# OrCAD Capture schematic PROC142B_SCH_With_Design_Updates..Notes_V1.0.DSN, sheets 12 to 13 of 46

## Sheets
12 10. USB TYPE-C POWER: size C; title: USB TYPE-C PD CONTROLLER AND POWER SUPPLY
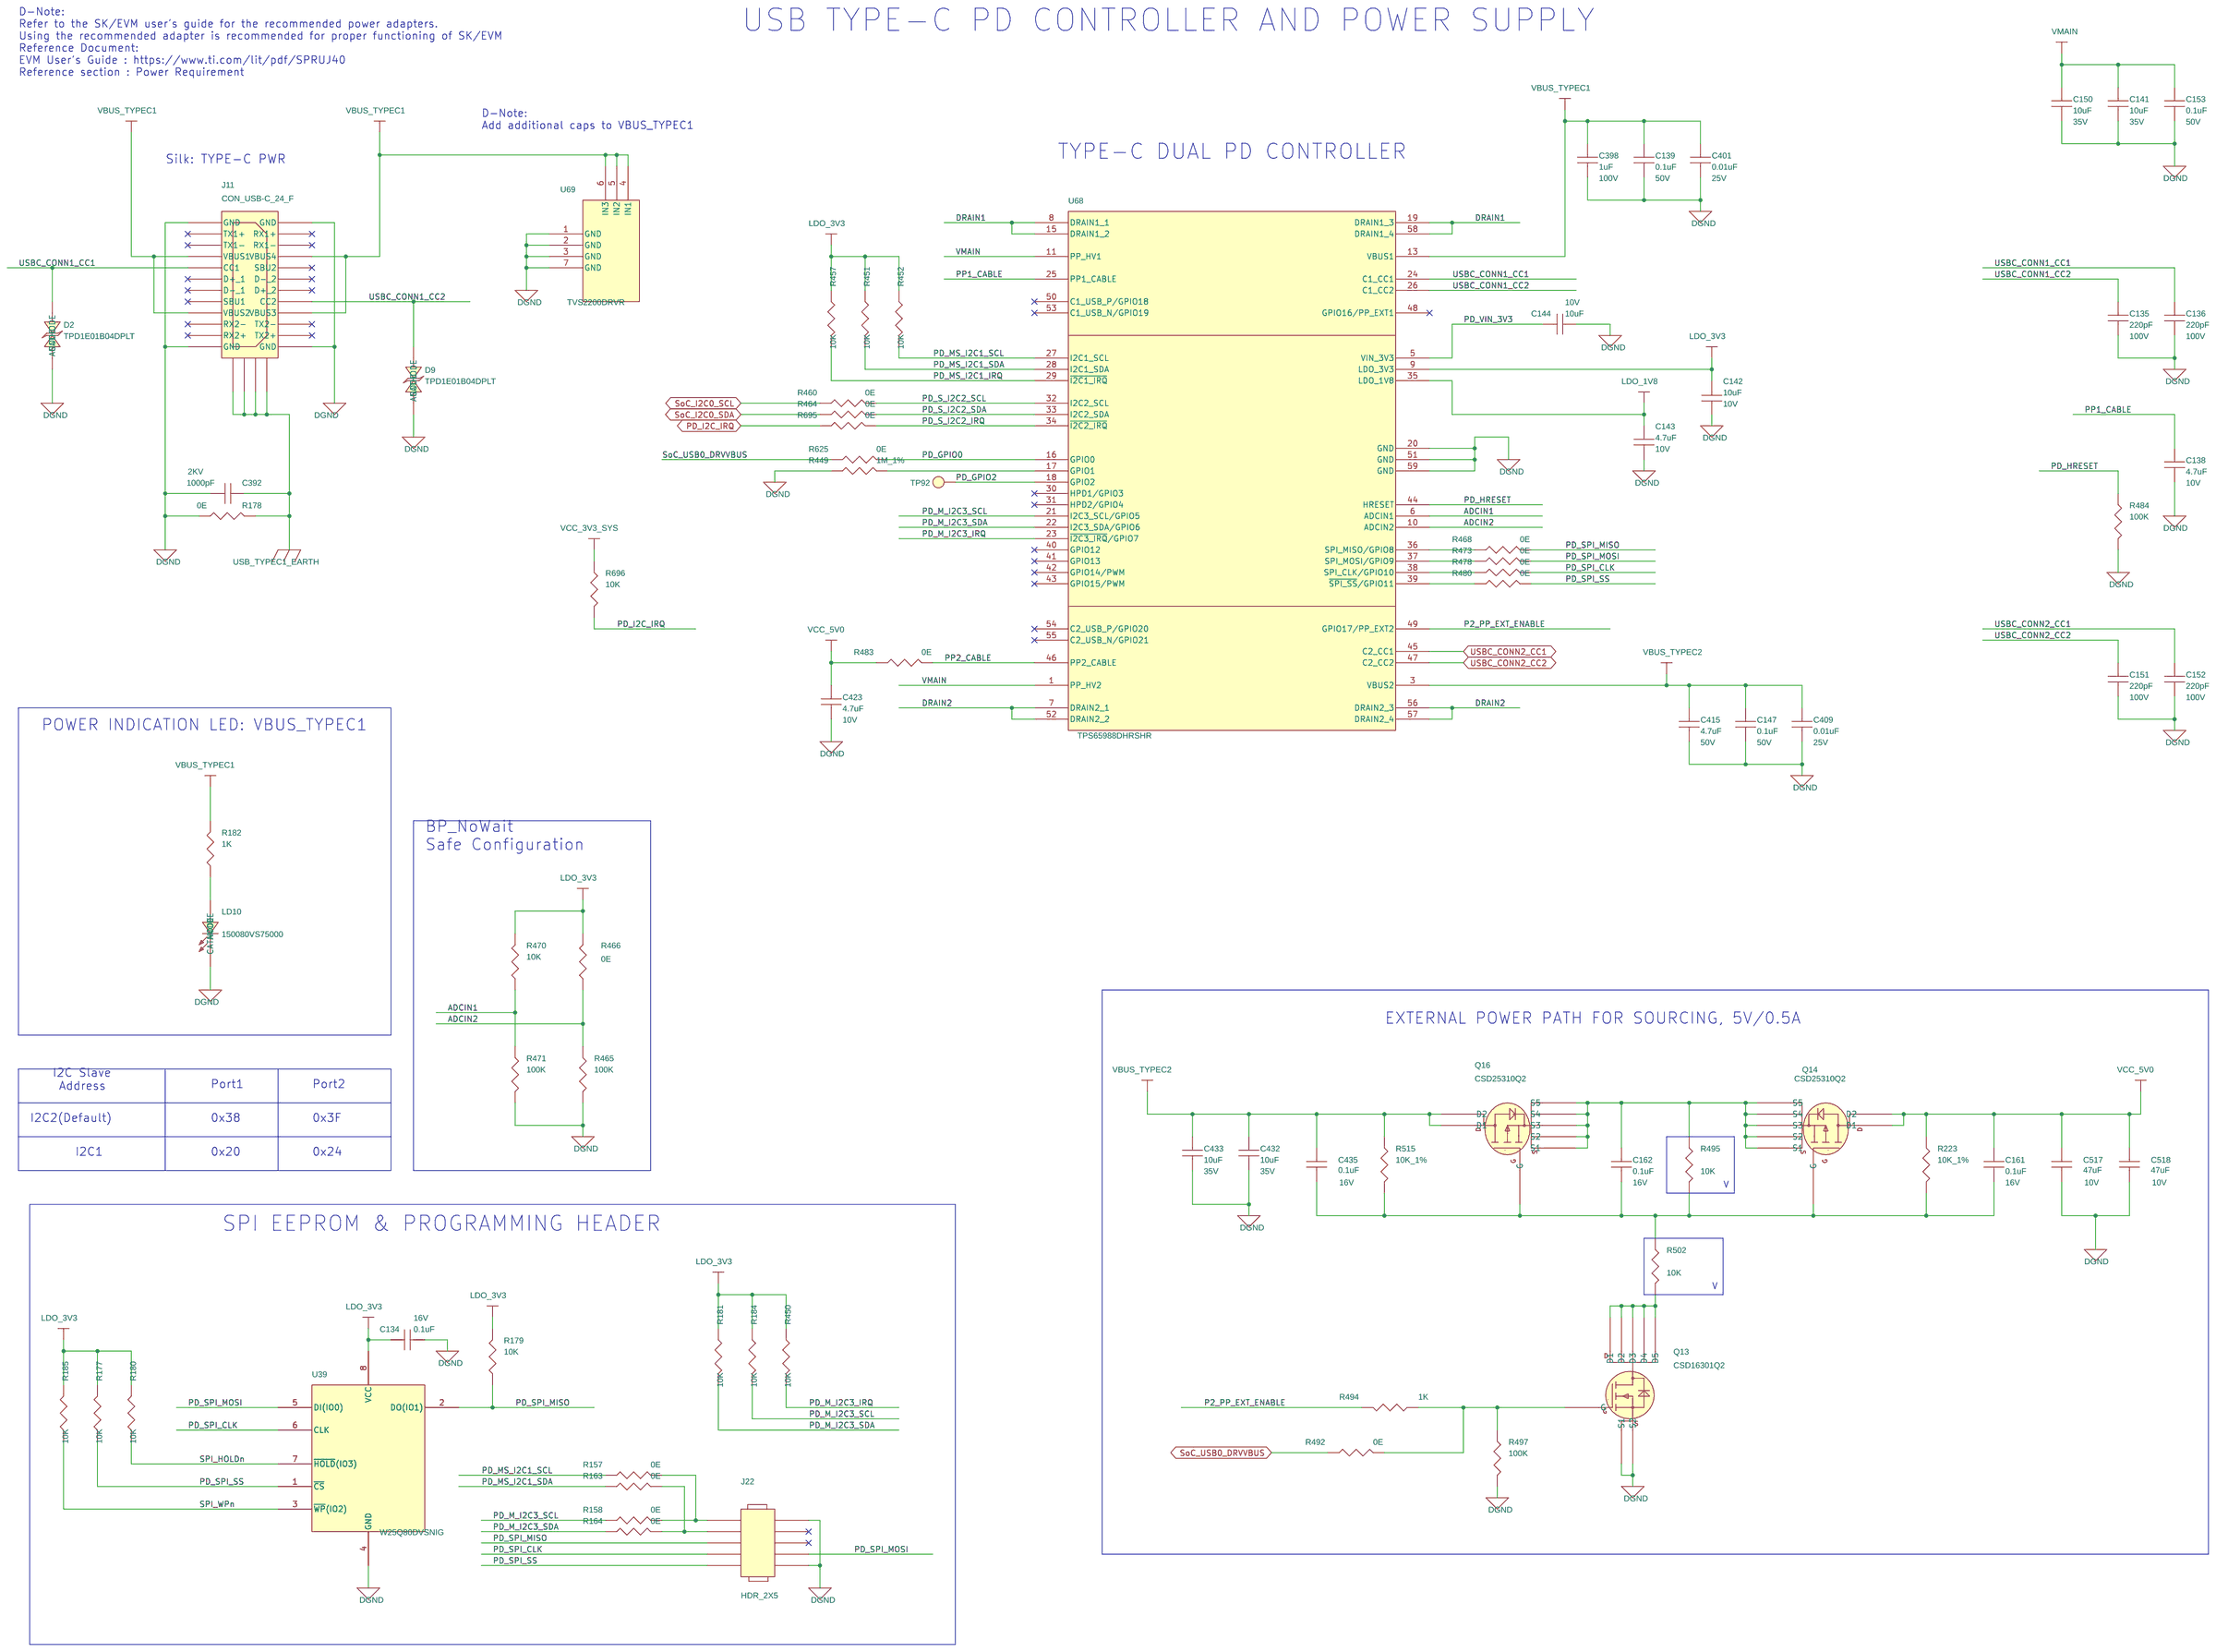
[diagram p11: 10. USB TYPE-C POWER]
13 11. PERIPHERAL POWER SUPPLY-1: size C; title: PERIPHERAL POWER SUPPLIES-1
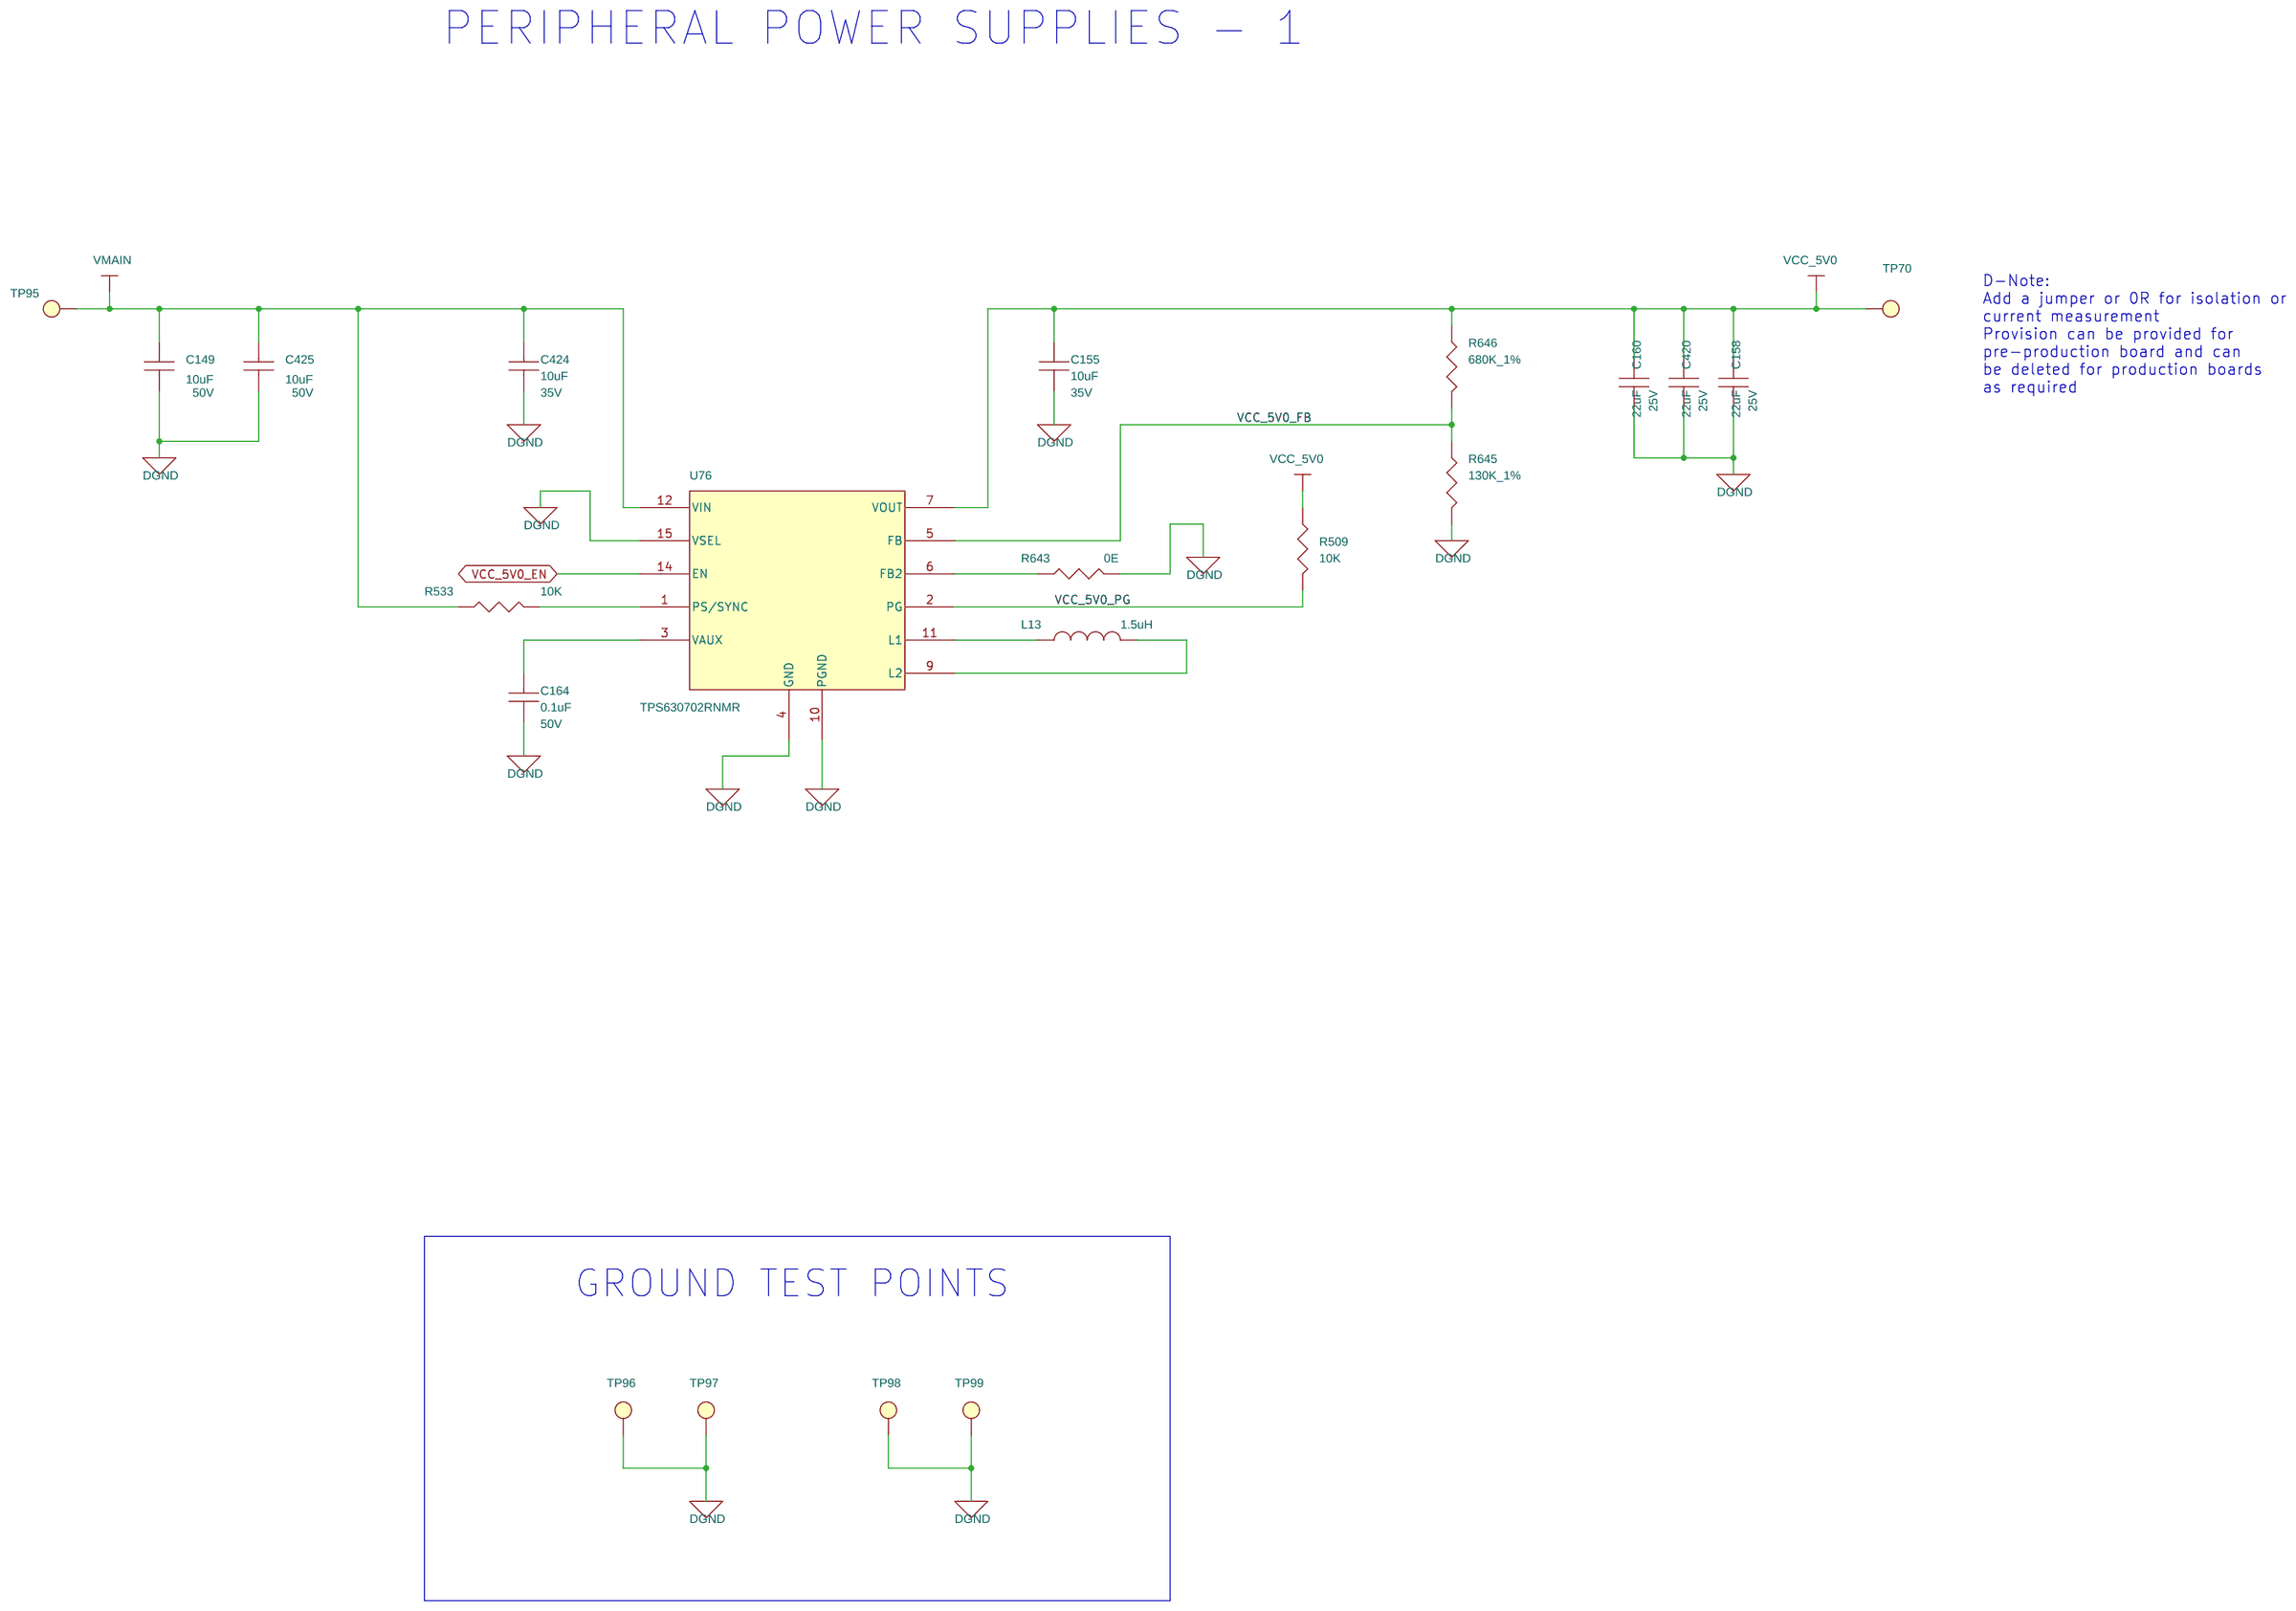
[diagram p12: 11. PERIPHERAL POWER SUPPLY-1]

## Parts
sheet 10. USB TYPE-C POWER
C134  0.1uF  [CAP0201_0-5]
C135  220pF  [CAP0402_0-75]
C136  220pF  [CAP0402_0-75]
C138  4.7uF  [CAP0402_0-75]
C139  0.1uF  [CAP0402_0-75]
C141  10uF  [CAP0603_1]
C142  10uF  [CAP0402_0-75]
C143  4.7uF  [CAP0402_0-75]
C144  10uF  [CAP0402_0-75]
C147  0.1uF  [CAP0402_0-75]
C150  10uF  [CAP0603_1]
C151  220pF  [CAP0402_0-75]
C152  220pF  [CAP0402_0-75]
C153  0.1uF  [CAP0402_0-75]
C161  0.1uF  [CAP0201_0-5]
C162  0.1uF  [CAP0201_0-5]
C392  1000pF  [CAP1206_1-75]
C398  1uF  [CAP0805_1-5]
C401  0.01uF  [CAP0201_0-5]
C409  0.01uF  [CAP0201_0-5]
C415  4.7uF  [CAP0805_1-5]
C423  4.7uF  [CAP0402_0-75]
C432  10uF  [CAP0603_1]
C433  10uF  [CAP0603_1]
C435  0.1uF  [CAP0201_0-5]
C517  47uF  [CAP1206_2]
C518  47uF  [CAP1206_2]
D2  TPD1E01B04DPLT  [DIO_DFN0201_0-4]
D9  TPD1E01B04DPLT  [DIO_DFN0201_0-4]
J11  CON_USB-C_24_F  [CON_USBC24_2012670_S_R_S_3-9]
J22  HDR_2X5  [HDR_2X5_PEC05DAAN_S_T_8-6]
LD10  150080VS75000  [LED_150080VS75000_80X50_SMD_0-8]
Q13  CSD16301Q2  [WSON6_CSD13202Q2_80X80_0-8]
Q14  CSD25310Q2  [SON6_CSD17313Q2_80X80]
Q16  CSD25310Q2  [SON6_CSD17313Q2_80X80]
R157  0E  [RES0201_0-5]
R158  0E  [RES0201_0-5]
R163  0E  [RES0201_0-5]
R164  0E  [RES0201_0-5]
R177  10K  [RES0201_0-5]
R178  0E  [RES0603_0-75]
R179  10K  [RES0201_0-5]
R180  10K  [RES0201_0-5]
R181  10K  [RES0201_0-5]
R182  1K  [RES0402_0-5]
R184  10K  [RES0201_0-5]
R185  10K  [RES0201_0-5]
R223  10K_1%  [RES0201_0-5]
R449  1M_1%  [RES0402_0-5]
R450  10K  [RES0201_0-5]
R451  10K  [RES0201_0-5]
R452  10K  [RES0201_0-5]
R457  10K  [RES0201_0-5]
R460  0E  [RES0201_0-5]
R464  0E  [RES0201_0-5]
R465  100K  [RES0402_0-5]
R466  0E  [RES0402_0-5]
R468  0E  [RES0201_0-5]
R470  10K  [RES0402_0-5]
R471  100K  [RES0402_0-5]
R473  0E  [RES0201_0-5]
R478  0E  [RES0201_0-5]
R480  0E  [RES0201_0-5]
R483  0E  [RES0402_0-5]
R484  100K  [RES0201_0-5]
R492  0E  [RES0201_0-5]
R494  1K  [RES0402_0-5]
R495  10K  [RES0201_0-5]
R497  100K  [RES0402_0-5]
R502  10K  [RES0201_0-5]
R515  10K_1%  [RES0201_0-5]
R625  0E  [RES0201_0-5]
R695  0E  [RES0201_0-5]
R696  10K  [RES0201_0-5]
TP92  TP20_SMD  [TP20_SMD]
U39  W25Q80DVSNIG  [SOIC8_1-8]
U68  TPS65988DHRSHR  [VQFN56_TPS65987D_280X280_1]
U69  TVS2200DRVR  [SON6_25-59_85X85_0-8]
sheet 11. PERIPHERAL POWER SUPPLY-1
C149  10uF  [CAP0805_1-5]
C155  10uF  [CAP0603_1]
C158  22uF  [CAP0805_1-5]
C160  22uF  [CAP0805_1-5]
C164  0.1uF  [CAP0402_0-75]
C420  22uF  [CAP0805_1-5]
C424  10uF  [CAP0603_1]
C425  10uF  [CAP0805_1-5]
L13  1.5uH  [IND_XFL4020_170X170_SMD_2-1]
R509  10K  [RES0402_0-5]
R533  10K  [RES0402_0-5]
R643  0E  [RES0201_0-5]
R645  130K_1%  [RES0402_0-5]
R646  680K_1%  [RES0402_0-5]
TP70  TP20_SMD  [TP20_SMD]
TP95  TP20_SMD  [TP20_SMD]
TP96  THRU HOLE  [TP_36X22]
TP97  THRU HOLE  [TP_36X22]
TP98  TP20_SMD  [TP20_SMD]
TP99  TP20_SMD  [TP20_SMD]
U76  TPS630702RNMR  [VQFNHR15_TPS630701_100X120_1]

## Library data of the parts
C134 C161 C162 C435 = CAP: CAP CERAMIC 0.1uF 16V 10% X5R 0201; Chkd/date: MANIRAJA/230118; Crtd /date: MANIRAJA/230118; Custom_Duty: 15%; Customs_HS_Code: 85322990; Distributor_name: DIGIKEY; Distributor_part_number: 490-14305-1-ND; Footprint Path: Y:\MIS_DATABASE\Library\ALTIUM_TOOL\PCB_FOOTPRINTS\Altium_Footprint_Lib.PcbLib; Height: 0.33MM; Library Path: Y:\MIS_DATABASE\Library\ALTIUM_TOOL\SCHEMATICS_PARTS\MS_DISCRETE_Library.schlib; Mfr_name: MURATA; Mfr_part_number: GRM033R61C104KE14D; Mistral Part No: 120009030072-R; Package: 0201; Part_type: CAPACITORS\CERAMIC; Project: TI_MAXIE_CPB; RoHS: RoHS; Temperature: -55°C+85°C; Tolerance: 10%; Voltage: 16V; Wattage: NA; Weight: 0.33mg; Datasheet: Y:\MIS_DATABASE\DATASHEETS\CAPACITORS\GRM033R61C104KE14.PDF
C135 C136 C151 C152 = CAP: CAP CERAMIC 220pF 100V 5% C0G(NP0) 0402; Chkd/date: MANIRAJA/061021; Crtd /date: ALVY/051021; Custom_Duty: 15%; Customs_HS_Code: 85322990; Distributor_name: DIGIKEY; Distributor_part_number: 490-GRM1555C2A221JE01DTR-ND; Footprint Path: Y:\MIS_DATABASE\Library\ALTIUM_TOOL\PCB_FOOTPRINTS\Altium_Footprint_Lib.PcbLib; Height: 0.55MM; Library Path: Y:\MIS_DATABASE\Library\ALTIUM_TOOL\SCHEMATICS_PARTS\MS_DISCRETE_Library.schlib; Mfr_name: MURATA; Mfr_part_number: GRM1555C2A221JE01D; Mistral Part No: 120021100001-R; Package: 0402; Part_type: CAPACITORS\CERAMIC; Project: TI_AM62x SKEVM_BRD; RoHS: RoHS; Temperature: -55°C+125°C; Tolerance: 5%; Voltage: 100V; Wattage: NA; Weight: 1.6mg; Datasheet: Y:\MIS_DATABASE\DATASHEETS\CAPACITORS\GRM1555C2A221JE01.PDF
C138 C143 C423 = CAP: CAP CERAMIC 4.7uF 10V 20% X5R 0402; Chkd/date: MANIRAJA/110718; Crtd /date: ALVY/110718; Custom_Duty: 15%; Customs_HS_Code: 85322990; Distributor_name: DIGIKEY; Distributor_part_number: 490-14306-1-ND; Footprint Path: Y:\MIS_DATABASE\Library\ALTIUM_TOOL\PCB_FOOTPRINTS\Altium_Footprint_Lib.PcbLib; Height: 0.65MM; Library Path: Y:\MIS_DATABASE\Library\ALTIUM_TOOL\SCHEMATICS_PARTS\MS_DISCRETE_Library.schlib; Mfr_name: MURATA; Mfr_part_number: GRM155R61A475MEAAD; Mistral Part No: 120012060002-R; Package: 0402; Part_type: CAPACITORS\CERAMIC; Project: TI_J7SVB_PCIE_ADD-ON-CARD; RoHS: RoHS; Temperature: -55°C+85°C; Tolerance: 20%; Voltage: 10V; Wattage: NA; Weight: 14mg; Datasheet: Y:\MIS_DATABASE\DATASHEETS\CAPACITORS\GRM155R61A475MEAAD.PDF
C139 C147 C153 C164 = CAP: CAP CERAMIC 0.1uF 50V 10% X7R 0402; Chkd/date: MANIRAJA/261020; Crtd /date: ALVY/211020; Custom_Duty: 15%; Customs_HS_Code: 85322990; Distributor_name: DIGIKEY; Distributor_part_number: 490-10700-1-ND; Footprint Path: Y:\MIS_DATABASE\Library\ALTIUM_TOOL\PCB_FOOTPRINTS\Altium_Footprint_Lib.PcbLib; Height: 0.55MM; Library Path: Y:\MIS_DATABASE\Library\ALTIUM_TOOL\SCHEMATICS_PARTS\MS_DISCRETE_Library.schlib; Mfr_name: MURATA; Mfr_part_number: GRM155R71H104KE14D; Mistral Part No: 120011100014-R; Package: 0402; Part_type: CAPACITORS\CERAMIC; Project: J7_CP; RoHS: RoHS; Temperature: -55°C+125°C; Tolerance: 10%; Voltage: 50V; Wattage: NA; Weight: 3.1mg; Datasheet: Y:\MIS_DATABASE\DATASHEETS\CAPACITORS\GRM155R71H104KE14.PDF
C141 C150 C155 C424 C432 C433 = CAP: CAP CERAMIC 10uF 35V 20% X5R 0603; Chkd/date: MANIRAJA/170519; Crtd /date: ALVY/160519; Custom_Duty: 15%; Customs_HS_Code: 85322990; Distributor_name: DIGIKEY; Distributor_part_number: 490-13248-1-ND; Footprint Path: Y:\MIS_DATABASE\Library\ALTIUM_TOOL\PCB_FOOTPRINTS\Altium_Footprint_Lib.PcbLib; Height: 1.00MM; Library Path: Y:\MIS_DATABASE\Library\ALTIUM_TOOL\SCHEMATICS_PARTS\MS_DISCRETE_Library.schlib; Mfr_name: MURATA; Mfr_part_number: GRM188R6YA106MA73D; Mistral Part No: 120019050016-R; Package: 0603; Part_type: CAPACITORS\CERAMIC; Project: BRUKER_SD820_COMMONDO; RoHS: RoHS; Temperature: -55°C+85°C; Tolerance: 20%; Voltage: 35V; Wattage: NA; Weight: 9mg; Datasheet: Y:\MIS_DATABASE\DATASHEETS\CAPACITORS\GRM188R6YA106MA73.PDF
C142 C144 = CAP: CAP CERAMIC 10uF 10V 20% X5R 0402; Chkd/date: MANIRAJA/300520; Crtd /date: ALVY/260520; Custom_Duty: 15%; Customs_HS_Code: 85322990; Distributor_name: DIGIKEY; Distributor_part_number: 490-GRM155R61A106ME11DTR-ND; Footprint Path: Y:\MIS_DATABASE\Library\ALTIUM_TOOL\PCB_FOOTPRINTS\Altium_Footprint_Lib.PcbLib; Height: 0.55MM; Library Path: Y:\MIS_DATABASE\Library\ALTIUM_TOOL\SCHEMATICS_PARTS\MS_DISCRETE_Library.schlib; Mfr_name: MURATA; Mfr_part_number: GRM155R61A106ME11D; Mistral Part No: 120013110019-R; Package: 0402; Part_type: CAPACITORS\CERAMIC; Project: QCS610_NANOSOM; RoHS: RoHS; Temperature: -55°C+85°C; Tolerance: 20%; Voltage: 10V; Wattage: NA; Weight: 3.1mg; Datasheet: Y:\MIS_DATABASE\DATASHEETS\CAPACITORS\MURATA-GXX-SER_NOV17.PDF
C392 = CAP: CAP CERAMIC 1000pF 2KV 10% X7R 1206; Chkd/date: SHREESHAIL/291106; Crtd /date: MAZHAR/281106; Custom_Duty: 15%; Customs_HS_Code: 85322990; Distributor_name: DIGIKEY; Distributor_part_number: 478-2956-1-ND; Footprint Path: Y:\MIS_DATABASE\Library\ALTIUM_TOOL\PCB_FOOTPRINTS\Altium_Footprint_Lib.PcbLib; Height: 1.52MM; Library Path: Y:\MIS_DATABASE\Library\ALTIUM_TOOL\SCHEMATICS_PARTS\MS_DISCRETE_Library.schlib; Mfr_name: AVX CORPORATION; Mfr_part_number: 1206GC102KAT1A; Mistral Part No: 120015080006-R; Package: 1206; Part_type: CAPACITORS\CERAMIC; Project: ADR1B; RoHS: RoHS; Temperature: -55°C+125°C; Tolerance: 10%; Voltage: 2KV; Wattage: NA; Weight: 16.2mg; Datasheet: Y:\MIS_DATABASE\DATASHEETS\CAPACITORS\AVX_HV-MLC.PDF
C398 = CAP: CAP CERAMIC 1uF 100V 10% X7S 0805; Chkd/date: MANIRAJA/160921; Crtd /date: ALVY/150921; Custom_Duty: 15%; Customs_HS_Code: 85322990; Distributor_name: DIGIKEY; Distributor_part_number: 490-14464-1-ND; Footprint Path: Y:\MIS_DATABASE\Library\ALTIUM_TOOL\PCB_FOOTPRINTS\Altium_Footprint_Lib.PcbLib; Height: 1.45MM; Library Path: Y:\MIS_DATABASE\Library\ALTIUM_TOOL\SCHEMATICS_PARTS\MS_DISCRETE_Library.schlib; Mfr_name: MURATA; Mfr_part_number: GRM21BC72A105KE01L; Mistral Part No: 120013030002-R; Package: 0805; Part_type: CAPACITORS\CERAMIC; Project: TI_AM62x SKEVM_BRD; RoHS: RoHS; Temperature: -55°C+125°C; Tolerance: 10%; Voltage: 100V; Wattage: NA; Weight: 6.4mg; Datasheet: Y:\MIS_DATABASE\DATASHEETS\CAPACITORS\GRM21BC72A105KE01.PDF
C401 C409 = CAP: CAP CERAMIC 0.01uF 25V 10% X5R 0201; Chkd/date: MANIRAJA/230118; Crtd /date: MANIRAJA/230118; Custom_Duty: 15%; Customs_HS_Code: 85322990; Distributor_name: DIGIKEY; Distributor_part_number: GRM033R61E103KA12J-ND; Footprint Path: Y:\MIS_DATABASE\Library\ALTIUM_TOOL\PCB_FOOTPRINTS\Altium_Footprint_Lib.PcbLib; Height: 0.33MM; Library Path: Y:\MIS_DATABASE\Library\ALTIUM_TOOL\SCHEMATICS_PARTS\MS_DISCRETE_Library.schlib; Mfr_name: MURATA; Mfr_part_number: GRM033R61E103KA12J; Mistral Part No: 120018010007-R; Package: 0201; Part_type: CAPACITORS\CERAMIC; Project: TI_MAXIE_CPB; RoHS: RoHS; Temperature: -55°C+85°C; Tolerance: 10%; Voltage: 25V; Wattage: NA; Weight: 0.33mg; Datasheet: Y:\MIS_DATABASE\DATASHEETS\CAPACITORS\GRM033R61E103KA12.PDF
C415 = CAP: CAP CERAMIC 4.7uF 50V 10% X5R 0805; Chkd/date: VASANTHA/281216; Crtd /date: BAVISH/290711; Custom_Duty: 15%; Customs_HS_Code: 85322990; Distributor_name: DIGIKEY; Distributor_part_number: 445-5980-1-ND; Footprint Path: Y:\MIS_DATABASE\Library\ALTIUM_TOOL\PCB_FOOTPRINTS\Altium_Footprint_Lib.PcbLib; Height: 1.45MM; Library Path: Y:\MIS_DATABASE\Library\ALTIUM_TOOL\SCHEMATICS_PARTS\MS_DISCRETE_Library.schlib; Mfr_name: TDK CORPORATION; Mfr_part_number: C2012X5R1H475K; Mistral Part No: 120011070010-R; Package: 0805; Part_type: CAPACITORS\CERAMIC; Project: OMAPL1_PEC20; RoHS: RoHS; Temperature: -55°C+85°C; Tolerance: 10%; Voltage: 50V; Wattage: NA; Weight: 5.5mg; Datasheet: Y:\MIS_DATABASE\DATASHEETS\CAPACITORS\TDK_C-SERIES.PDF
C517 C518 = CAP: CAP CERAMIC 47uF 10V 20% X5R 1206; Chkd/date: USMAN/121213; Crtd /date: USMAN/121213; Custom_Duty: 15%; Customs_HS_Code: 85322990; Distributor_name: DIGIKEY; Distributor_part_number: 490-5528-1-ND; Footprint Path: Y:\MIS_DATABASE\Library\ALTIUM_TOOL\PCB_FOOTPRINTS\Altium_Footprint_Lib.PcbLib; Height: 1.80MM; Library Path: Y:\MIS_DATABASE\Library\ALTIUM_TOOL\SCHEMATICS_PARTS\MS_DISCRETE_Library.schlib; Mfr_name: MURATA; Mfr_part_number: GRM31CR61A476ME15L; Mistral Part No: 120013120015-R; Package: 1206; Part_type: CAPACITORS\CERAMIC; Project: DMP; RoHS: RoHS; Temperature: -55°C+85°C; Tolerance: 20%; Voltage: 10V; Wattage: NA; Weight: 40mg; Datasheet: Y:\MIS_DATABASE\DATASHEETS\CAPACITORS\MURATA-GXX-SER_NOV17.PDF
D2 D9 = DIODE_TVS_DUAL: DIODE 1CH ESD PROTECTION FOR USB TYPE-C AND THUNDERBOLT3 X2SON2; Chkd/date: MANIRAJA/230920; Crtd /date: ALVY/230920; Custom_Duty: 15%; Customs_HS_Code: 85412900; Distributor_name: DIGIKEY; Distributor_part_number: 296-44484-1-ND; Footprint Path: Y:\MIS_DATABASE\Library\ALTIUM_TOOL\PCB_FOOTPRINTS\Altium_Footprint_Lib.PcbLib; Height: 0.32MM; Library Path: Y:\MIS_DATABASE\Library\ALTIUM_TOOL\SCHEMATICS_PARTS\MS_DISCRETE_Library.schlib; Mfr_name: TEXAS INSTRUMENTS; Mistral Part No: 130020090037-R; Package: X2SON2; Part_type: DIODE\TVS; Project: AM64X_SKEVM; RoHS: RoHS; Temperature: -40°C+125°C; Tolerance: NA; Voltage: NA; Wattage: NA; Weight: 0.2mg; Datasheet: Y:\MIS_DATABASE\DATASHEETS\DISCRETES\DIODES\TPD1E01B04.PDF
J11 = CON_USB-C_24_1240183621: CON USB-C TYPE 24POS FEMALE RT SMD; Chkd/date: MANIRAJA/050618; Crtd /date: ALVY/040618; Custom_Duty: 24%; Customs_HS_Code: 85369090; Distributor_name: DIGIKEY; Distributor_part_number: WM17992CT-ND; Footprint Path: Y:\MIS_DATABASE\Library\ALTIUM_TOOL\PCB_FOOTPRINTS\Altium_Footprint_Lib.PcbLib; Height: 3.86MM; Library Path: Y:\MIS_DATABASE\Library\ALTIUM_TOOL\SCHEMATICS_PARTS\MS_CONNECTOR_Library.schlib; Mfr_name: MOLEX; Mfr_part_number: 2012670005; Mistral Part No: 150018060002-R; Package: SMD; Part_type: CONNECTOR\USB; Project: TI_J7SVB_USB_ADD-ON-CARD; RoHS: RoHS; Temperature: -40°C+105°C; Tolerance: NA; Voltage: NA; Wattage: NA; Weight: 0.686g; Datasheet: Y:\MIS_DATABASE\DATASHEETS\CONNECTORS\2012670X.PDF
J22 = HEADER_5X2: CON HDR 2X5 2.54MM PITCH ST TH; Chkd/date: MANIRAJA/060821; Crtd /date: ALVY/060821; Custom_Duty: 24%; Customs_HS_Code: 85369090; Distributor_name: DIGIKEY; Distributor_part_number: S2012E-05-ND; Footprint Path: Y:\MIS_DATABASE\Library\ALTIUM_TOOL\PCB_FOOTPRINTS\Altium_Footprint_Lib.PcbLib; Height: 8.58MM; Library Path: Y:\MIS_DATABASE\Library\ALTIUM_TOOL\SCHEMATICS_PARTS\MS_CONNECTOR_Library.schlib; Mfr_name: SULLINS CONNECTOR; Mfr_part_number: PEC05DAAN; Mistral Part No: 150021080010-R; Package: THRU-HOLE; Part_type: CONNECTOR\HEADERS; Project: TI_AM335x SK_BRD; RoHS: RoHS; Temperature: -65°C+125°C; Tolerance: NA; Voltage: NA; Wattage: NA; Weight: NA; Datasheet: Y:\MIS_DATABASE\DATASHEETS\CONNECTORS\XXCXXDXXN.PDF
LD10 = DIODE_LED: DIODE LED BRIGHT GREEN SMD; Chkd/date: MANIRAJA/180820; Crtd /date: ALVY/180820; Custom_Duty: 24%; Customs_HS_Code: 85439000; Distributor_name: DIGIKEY; Distributor_part_number: 732-4986-1-ND; Footprint Path: Y:\MIS_DATABASE\Library\ALTIUM_TOOL\PCB_FOOTPRINTS\Altium_Footprint_Lib.PcbLib; Height: 0.80MM; Library Path: Y:\MIS_DATABASE\Library\ALTIUM_TOOL\SCHEMATICS_PARTS\MS_OPTO_Library.schlib; Mfr_name: WURTH ELECTRONICS; Mistral Part No: 130020080012-R; Package: SMD; Part_type: OPTO\LED; Project: AM64x_EVM_BRD; RoHS: RoHS; Temperature: -40°C+85°C; Tolerance: NA; Voltage: NA; Wattage: NA; Weight: 10mg; Datasheet: Y:\MIS_DATABASE\DATASHEETS\DISCRETES\LEDS\150080VS75000.PDF
Q13 = MOSFET_CSD17313Q2: IC MOSFET N-CHANNEL NEXFET 25V WSON6; Chkd/date: ALVY/071220; Crtd /date: MANIRAJA/071220; Custom_Duty: 15%; Customs_HS_Code: 85423100; Distributor_name: DIGIKEY; Distributor_part_number: 296-25260-1-ND; Footprint Path: Y:\MIS_DATABASE\Library\ALTIUM_TOOL\PCB_FOOTPRINTS\Altium_Footprint_Lib.PcbLib; Height: 0.80MM; Library Path: Y:\MIS_DATABASE\Library\ALTIUM_TOOL\SCHEMATICS_PARTS\MS_MOSFET_Library.schlib; Mfr_name: TEXAS INSTRUMENTS; Mistral Part No: 142020120008-R; Package: WSON6; Part_type: ICS\POWER\MOSFET; Project: TI_AM243x LP EVM; RoHS: RoHS; Temperature: -55°C+150°C; Tolerance: NA; Voltage: NA; Wattage: NA; Weight: 8.7mg; Datasheet: Y:\MIS_DATABASE\DATASHEETS\ICS\POWER\CSD16301Q2.PDF
Q14 Q16 = MOSFET_CSD25310Q2: IC MOSFET P-CHANNEL WSON6; Chkd/date: VASANTHA/191215; Crtd /date: VASANTHA/191215; Custom_Duty: 15%; Customs_HS_Code: 85423100; Distributor_name: DIGIKEY; Distributor_part_number: 296-38915-1-ND; Height: 0.85MM; Mfr_name: TEXAS INSTRUMENTS; Mistral Part No: 142015120011-R; Package: WSON6; Part_type: ICS\POWER\MOSFET; Project: DUET BOARD; RoHS: RoHS; Temperature: -55°C+150°C; Tolerance: NA; Voltage: NA; Wattage: NA; Weight: NA; Datasheet: Y:\MIS_DATABASE\DATASHEETS\DISCRETES\TRANSISTORS_FETS\CSD25310Q2.PDF
R157 R158 R163 R164 R460 R464 R468 R473 R478 R480 R492 R625 R643 R695 = RESISTOR: RES 0E 1/20W 5% 0201; Chkd/date: NAVEED/301214; Crtd /date: MUDDU/120710; Custom_Duty: 15%; Customs_HS_Code: 85332119; Distributor_name: DIGIKEY; Distributor_part_number: 311-0.0NCT-ND; Footprint Path: Y:\MIS_DATABASE\Library\ALTIUM_TOOL\PCB_FOOTPRINTS\Altium_Footprint_Lib.PcbLib; Height: 0.26MM; Library Path: Y:\MIS_DATABASE\Library\ALTIUM_TOOL\SCHEMATICS_PARTS\MS_DISCRETE_Library.schlib; Mfr_name: YAGEO AMERICA; Mfr_part_number: RC0201JR-070RL; Mistral Part No: 110010070067-R; Package: 0201; Part_type: RESISTORS\FIXED; Project: PB_BUGBASE; RoHS: RoHS; Temperature: -55°C+125°C; Tolerance: 5%; Voltage: NA; Wattage: 1/20W; Weight: 0.17mg; Datasheet: Y:\MIS_DATABASE\DATASHEETS\RESISTORS\RCXXXXL-SER_MAR18.PDF
R177 R179-R181 R184 R185 R450-R452 R457 R495 R502 R696 = RESISTOR: RES 10K 1/20W 5% 0201; Chkd/date: MANIRAJA/050517; Crtd /date: MANIRAJA/050517; Custom_Duty: 15%; Customs_HS_Code: 85332119; Distributor_name: DIGIKEY; Distributor_part_number: 311-10KNCT-ND; Footprint Path: Y:\MIS_DATABASE\Library\ALTIUM_TOOL\PCB_FOOTPRINTS\Altium_Footprint_Lib.PcbLib; Height: 0.26MM; Library Path: Y:\MIS_DATABASE\Library\ALTIUM_TOOL\SCHEMATICS_PARTS\MS_DISCRETE_Library.schlib; Mfr_name: YAGEO AMERICA; Mfr_part_number: RC0201JR-0710KL; Mistral Part No: 110010070051-R; Package: 0201; Part_type: RESISTORS\FIXED; Project: GOLDEN-I LITE; RoHS: RoHS; Temperature: -55°C+125°C; Tolerance: 5%; Voltage: NA; Wattage: 1/20W; Weight: 0.17mg; Datasheet: Y:\MIS_DATABASE\DATASHEETS\RESISTORS\RCXXXXL-SER_MAR18.PDF
R178 = RESISTOR: RES 0E 1/10W 5% 0603; Chkd/date: MANIRAJA/051217; Crtd /date: BAVISH/180211; Custom_Duty: 15%; Customs_HS_Code: 85332119; Distributor_name: DIGIKEY; Distributor_part_number: 311-0.0GRCT-ND; Footprint Path: Y:\MIS_DATABASE\Library\ALTIUM_TOOL\PCB_FOOTPRINTS\Altium_Footprint_Lib.PcbLib; Height: 0.55MM; Library Path: Y:\MIS_DATABASE\Library\ALTIUM_TOOL\SCHEMATICS_PARTS\MS_DISCRETE_Library.schlib; Manufacturer: YAGEO AMERICA; Mfr_name: PANASONIC-ECG; Mfr_part_number: RC0603JR-070RL; Mistral Part No: 110011020013-R; Package: 0603; Part_type: RESISTORS\FIXED; Project: KENNEL; RoHS: RoHS; Temperature: -55°C+155°C; Tolerance: 5%; Voltage: NA; Wattage: 1/10W; Weight: 2mg; Datasheet: Y:\MIS_DATABASE\DATASHEETS\RESISTORS\RCXXXXL-SER_MAR18.PDF
R182 R494 = RESISTOR: RES 1K 1/10W 5% 0402; Chkd/date: VASANTHA/201216; Crtd /date: MAZHAR/230805; Custom_Duty: 15%; Customs_HS_Code: 85332119; Distributor_name: DIGIKEY; Distributor_part_number: P1.0KJCT-ND; Footprint Path: Y:\MIS_DATABASE\Library\ALTIUM_TOOL\PCB_FOOTPRINTS\Altium_Footprint_Lib.PcbLib; Height: 0.40MM; Library Path: Y:\MIS_DATABASE\Library\ALTIUM_TOOL\SCHEMATICS_PARTS\MS_DISCRETE_Library.schlib; Mfr_name: PANASONIC-ECG; Mfr_part_number: ERJ-2GEJ102X; Mistral Part No: 110009030400-R; Package: 0402; Part_type: RESISTORS\FIXED; Project: HSE; RoHS: RoHS; Temperature: -55°C+155°C; Tolerance: 5%; Voltage: NA; Wattage: 1/10W; Weight: 0.8mg; Datasheet: Y:\MIS_DATABASE\DATASHEETS\RESISTORS\PAN-ERJSER_NOV17.PDF
R223 R515 = RESISTOR: RES 10K 1/20W 1% 0201; Chkd/date: MANIRAJA/260618; Crtd /date: ALVY/260618; Custom_Duty: 15%; Customs_HS_Code: 85332119; Distributor_name: DIGIKEY; Distributor_part_number: 541-10.0KABCT-ND; Footprint Path: Y:\MIS_DATABASE\Library\ALTIUM_TOOL\PCB_FOOTPRINTS\Altium_Footprint_Lib.PcbLib; Height: 0.28MM; Library Path: Y:\MIS_DATABASE\Library\ALTIUM_TOOL\SCHEMATICS_PARTS\MS_DISCRETE_Library.schlib; Mfr_name: VISHAY; Mfr_part_number: CRCW020110K0FNED; Mistral Part No: 110018060032-R; Package: 0201; Part_type: RESISTORS\FIXED; Project: NEXTNAV_LPRX_BOARD; RoHS: RoHS; Temperature: -55°C+155°C; Tolerance: 1%; Voltage: NA; Wattage: 1/20W; Weight: 0.17mg; Datasheet: Y:\MIS_DATABASE\DATASHEETS\RESISTORS\CRCW0201.PDF
R449 = RESISTOR: RES 1M 1/16W 1% 0402; Chkd/date: MANIRAJA/190319; Crtd /date: MANIRAJA/190319; Custom_Duty: 15%; Customs_HS_Code: 85332119; Distributor_name: DIGIKEY; Distributor_part_number: 311-1.00MLRCT-ND; Footprint Path: Y:\MIS_DATABASE\Library\ALTIUM_TOOL\PCB_FOOTPRINTS\Altium_Footprint_Lib.PcbLib; Height: 0.40MM; Library Path: Y:\MIS_DATABASE\Library\ALTIUM_TOOL\SCHEMATICS_PARTS\MS_DISCRETE_Library.schlib; Mfr_name: YAGEO AMERICA; Mfr_part_number: RC0402FR-071ML; Mistral Part No: 110014060045-R; Package: 0402; Part_type: RESISTORS\FIXED; Project: G4SLIM; RoHS: RoHS; Temperature: -55°C+155°C; Tolerance: 1%; Voltage: NA; Wattage: 1/16W; Weight: 0.65mg; Datasheet: Y:\MIS_DATABASE\DATASHEETS\RESISTORS\RCXXXXL-SER_MAR18.PDF
R465 R471 R497 = RESISTOR: RES 100K 1/16W 5% 0402; Chkd/date: MANIRAJA/100717; Crtd /date: MANIRAJA/100717; Custom_Duty: 15%; Customs_HS_Code: 85332119; Distributor_name: DIGIKEY; Distributor_part_number: 311-100KJRCT-ND; Footprint Path: Y:\MIS_DATABASE\Library\ALTIUM_TOOL\PCB_FOOTPRINTS\Altium_Footprint_Lib.PcbLib; Height: 0.40MM; Library Path: Y:\MIS_DATABASE\Library\ALTIUM_TOOL\SCHEMATICS_PARTS\MS_DISCRETE_Library.schlib; Mfr_name: YAGEO AMERICA; Mfr_part_number: RC0402JR-07100KL; Mistral Part No: 110011060002-R; Package: 0402; Part_type: RESISTORS\FIXED; Project: DM8147_PCI CARD; RoHS: RoHS; Temperature: -55°C+155°C; Tolerance: 5%; Voltage: NA; Wattage: 1/16W; Weight: 0.65mg; Datasheet: Y:\MIS_DATABASE\DATASHEETS\RESISTORS\RCXXXXL-SER_MAR18.PDF
R466 R483 = RESISTOR: RES 0E 1/16W JUMPER 0402; Chkd/date: VASANTHA/201216; Crtd /date: MUDDU/190810; Custom_Duty: 15%; Customs_HS_Code: 85332119; Distributor_name: DIGIKEY; Distributor_part_number: 541-0.0JCT-ND; Footprint Path: Y:\MIS_DATABASE\Library\ALTIUM_TOOL\PCB_FOOTPRINTS\Altium_Footprint_Lib.PcbLib; Height: 0.40MM; Library Path: Y:\MIS_DATABASE\Library\ALTIUM_TOOL\SCHEMATICS_PARTS\MS_DISCRETE_Library.schlib; Mfr_name: VISHAY; Mfr_part_number: CRCW04020000Z0ED; Mistral Part No: 110010080019-R; Package: 0402; Part_type: RESISTORS\FIXED; Project: PB_BUGBASE; RoHS: RoHS; Temperature: -55°C+155°C; Tolerance: NA; Voltage: NA; Wattage: 1/16W; Weight: 0.65mg; Datasheet: Y:\MIS_DATABASE\DATASHEETS\RESISTORS\CRCW0603.PDF
R470 R509 R533 = RESISTOR: RES 10K 1/16W 5% 0402; Chkd/date: MANIRAJA/120219; Crtd /date: MANIRAJA/120219; Custom_Duty: 15%; Customs_HS_Code: 85332119; Distributor_name: DIGIKEY; Distributor_part_number: 541-10KJCT-ND; Footprint Path: Y:\MIS_DATABASE\Library\ALTIUM_TOOL\PCB_FOOTPRINTS\Altium_Footprint_Lib.PcbLib; Height: 0.40MM; Library Path: Y:\MIS_DATABASE\Library\ALTIUM_TOOL\SCHEMATICS_PARTS\MS_DISCRETE_Library.schlib; Mfr_name: VISHAY; Mfr_part_number: CRCW040210K0JNED; Mistral Part No: 110011060021-R; Package: 0402; Part_type: RESISTORS\FIXED; Project: NEXTNAV_ORBIT_MODULE; RoHS: RoHS; Temperature: -55°C+155°C; Tolerance: 5%; Voltage: NA; Wattage: 1/16W; Weight: 0.65mg; Datasheet: Y:\MIS_DATABASE\DATASHEETS\RESISTORS\CRCW0603.PDF
R484 = RESISTOR: RES 100K 1/20W 5% 0201; Chkd/date: VASANTHA/061216; Crtd /date: MAZHAR/141105; Custom_Duty: 15%; Customs_HS_Code: 85332119; Distributor_name: DIGIKEY; Distributor_part_number: P100KAGCT-ND; Footprint Path: Y:\MIS_DATABASE\Library\ALTIUM_TOOL\PCB_FOOTPRINTS\Altium_Footprint_Lib.PcbLib; Height: 0.26MM; Library Path: Y:\MIS_DATABASE\Library\ALTIUM_TOOL\SCHEMATICS_PARTS\MS_DISCRETE_Library.schlib; Mfr_name: PANASONIC-ECG; Mfr_part_number: ERJ-1GEJ104C; Mistral Part No: 110009030176-R; Package: 0201; Part_type: RESISTORS\FIXED; Project: J30; RoHS: RoHS; Temperature: -55°C+125°C; Tolerance: 5%; Voltage: NA; Wattage: 1/20W; Weight: 0.15mg; Datasheet: Y:\MIS_DATABASE\DATASHEETS\RESISTORS\PAN-ERJXGE-FEB06.PDF
TP70 TP92 TP95 TP98 TP99 = TESTPOINT: TESTPOINT CIR 20 SMD; Chkd/date: SHREESHAIL/171006; Crtd /date: MAZHAR/171006; Custom_Duty: NA; Customs_HS_Code: NA; Distributor_name: NA; Distributor_part_number: NA; Footprint Path: Y:\MIS_DATABASE\Library\ALTIUM_TOOL\PCB_FOOTPRINTS\Altium_Footprint_Lib.PcbLib; Height: NA; Library Path: Y:\MIS_DATABASE\Library\ALTIUM_TOOL\SCHEMATICS_PARTS\MS_DISCRETE_Library.schlib; MECHANICAL 3D STEP FILE: NA; Mfr_name: LOCAL; Mistral Part No: NA; Package: SMD; Project: BT MODULE_CSRBC04; RoHS: NA; Temperature: NA; Tolerance: NA; Voltage: NA; Wattage: NA; Weight: NA; Datasheet: NA
U39 = W25Q80BWSNIG_SOIC8: IC SERIAL FLASH MEMORY SOIC8; Chkd/date: VASANTHA/150217; Crtd /date: MANIRAJA/150217; Custom_Duty: 15%; Customs_HS_Code: 85423100; Distributor_name: DIGIKEY; Distributor_part_number: W25Q80DVSNIG CT-ND; Height: 1.75MM; Mfr_name: WINBOND; Mfr_part_number: W25Q80DVSNIG-TR; Mistral Part No: 141117020010-R; Package: SOIC8; Part_type: ICS\DIGITAL\MEMORY; Project: SD820_NANO_SOM; RoHS: RoHS; Temperature: -40°C+85°C; Tolerance: NA; Voltage: NA; Wattage: NA; Weight: NA; Datasheet: Y:\MIS_DATABASE\DATASHEETS\ICS\MEMORY\W25Q80DVSS.PDF
U68 = TPS65988DJ_VQFN56: IC 2-PORT USB TYPE-C AND USB PD CONTROLLER WITH INTEGRATED POWER SWITCH VQFN56; Chkd/date: MANIRAJA/290721; Crtd /date: ALVY/280721; Custom_Duty: 15%; Customs_HS_Code: 85423100; Distributor_name: DIGIKEY; Distributor_part_number: 296-52068-1-ND; Footprint Path: Y:\MIS_DATABASE\Library\ALTIUM_TOOL\PCB_FOOTPRINTS\Altium_Footprint_Lib.PcbLib; Height: 1.00MM; Library Path: Y:\MIS_DATABASE\Library\ALTIUM_TOOL\SCHEMATICS_PARTS\MS_MISCPOWER_Library.schlib; Mfr_name: TEXAS INSTRUMENTS; Mistral Part No: 142021070017-R; Package: VQFN56; Part_type: ICS\POWER\MANAGEMENT; Project: TI_AM62x_SKEVM; RoHS: RoHS; Temperature: -10°C+75°C; Tolerance: NA; Voltage: NA; Wattage: NA; Weight: 127.6mg; Datasheet: Y:\MIS_DATABASE\DATASHEETS\ICS\POWER\TPS65988DHRSHR.PDF
U69 = TVS2200_WSON6: IC 22V FLAT-CLAMP SURGE PROTECTION DEVICE WSON6; Chkd/date: MANIRAJA/011021; Crtd /date: ALVY/011021; Custom_Duty: 15%; Customs_HS_Code: 85423100; Distributor_name: DIGIKEY; Distributor_part_number: 296-52187-1-ND; Footprint Path: Y:\MIS_DATABASE\Library\ALTIUM_TOOL\PCB_FOOTPRINTS\Altium_Footprint_Lib.PcbLib; Height: 0.80MM; Library Path: Y:\MIS_DATABASE\Library\ALTIUM_TOOL\SCHEMATICS_PARTS\MS_MISCPOWER_Library.schlib; Mfr_name: TEXAS INSTRUMENTS; Mistral Part No: 142021100001-R; Package: WSON6; Part_type: ICS\POWER; Project: TI_AM62x SKEVM_BRD; RoHS: RoHS; Temperature: -40°C+125°C; Tolerance: NA; Voltage: NA; Wattage: NA; Weight: 12mg; Datasheet: Y:\MIS_DATABASE\DATASHEETS\ICS\POWER\TVS2200.PDF
C149 C425 = CAP: CAP CERAMIC 10uF 50V 10% X5R 0805; Chkd/date: MANIRAJA/010321; Crtd /date: ALVY/010321; Custom_Duty: 15%; Customs_HS_Code: 85322990; Distributor_name: DIGIKEY; Distributor_part_number: 490-18663-1-ND; Footprint Path: Y:\MIS_DATABASE\Library\ALTIUM_TOOL\PCB_FOOTPRINTS\Altium_Footprint_Lib.PcbLib; Height: 1.45MM; Library Path: Y:\MIS_DATABASE\Library\ALTIUM_TOOL\SCHEMATICS_PARTS\MS_DISCRETE_Library.schlib; Mfr_name: MURATA; Mfr_part_number: GRM21BR61H106KE43L; Mistral Part No: 120021030002-R; Package: 0805; Part_type: CAPACITORS\CERAMIC; Project: J7ES_SK_BRD; RoHS: RoHS; Temperature: -55°C+85°C; Tolerance: 10%; Voltage: 50V; Wattage: NA; Weight: 6.4mg; Datasheet: Y:\MIS_DATABASE\DATASHEETS\CAPACITORS\GRM21BR61H106KE43.PDF
C158 C160 C420 = CAP: CAP CERAMIC 22uF 25V 20% X5R 0805; Chkd/date: MANIRAJA/110718; Crtd /date: ALVY/110718; Custom_Duty: 15%; Customs_HS_Code: 85322990; Distributor_name: DIGIKEY; Distributor_part_number: 490-14661-1-ND; Footprint Path: Y:\MIS_DATABASE\Library\ALTIUM_TOOL\PCB_FOOTPRINTS\Altium_Footprint_Lib.PcbLib; Height: 1.45MM; Library Path: Y:\MIS_DATABASE\Library\ALTIUM_TOOL\SCHEMATICS_PARTS\MS_DISCRETE_Library.schlib; Mfr_name: MURATA; Mfr_part_number: GRM21BR61E226ME44K; Mistral Part No: 120013120018-R; Package: 0805; Part_type: CAPACITORS\CERAMIC; Project: TI_J7SVB_PCIE_ADD-ON-CARD; RoHS: RoHS; Temperature: -55°C+85°C; Tolerance: 20%; Voltage: 25V; Wattage: NA; Weight: 9.5mg; Datasheet: Y:\MIS_DATABASE\DATASHEETS\CAPACITORS\GRM21BR61E226ME44K.PDF
L13 = INDUCTOR: IND POWER 1.5uH 9.1A 20% SMD; Chkd/date: MANIRAJA/101019; Crtd /date: MANIRAJA/101019; Custom_Duty: 24%; Customs_HS_Code: 85437099; Distributor_name: MOUSER; Distributor_part_number: 994-XFL4020-152MEB; Footprint Path: Y:\MIS_DATABASE\Library\ALTIUM_TOOL\PCB_FOOTPRINTS\Altium_Footprint_Lib.PcbLib; Height: 2.10MM; Library Path: Y:\MIS_DATABASE\Library\ALTIUM_TOOL\SCHEMATICS_PARTS\MS_DISCRETE_Library.schlib; Mfr_name: COIL CRAFT; Mfr_part_number: XFL4020-152MEB; Mistral Part No: 130019100011-R; Package: SMD; Project: NPOL_UAIS_CONTROLLER-CARD; RoHS: RoHS; Temperature: -40°C+125°C; Tolerance: 20%; Voltage: NA; Wattage: NA; Weight: 169mg; Datasheet: Y:\MIS_DATABASE\DATASHEETS\DISCRETES\INDUCTORS\XFL4020.PDF
R645 = RESISTOR: RES 130K 1/10W 1% 0402; Chkd/date: MAZHAR/150611; Crtd /date: BAVISH/020611; Custom_Duty: 15%; Customs_HS_Code: 85332119; Distributor_name: DIGIKEY; Distributor_part_number: P130KLCT-ND; Footprint Path: Y:\MIS_DATABASE\Library\ALTIUM_TOOL\PCB_FOOTPRINTS\Altium_Footprint_Lib.PcbLib; Height: 0.40MM; Library Path: Y:\MIS_DATABASE\Library\ALTIUM_TOOL\SCHEMATICS_PARTS\MS_DISCRETE_Library.schlib; Mfr_name: PANASONIC-ECG; Mfr_part_number: ERJ-2RKF1303X; Mistral Part No: 110011060012-R; Package: 0402; Part_type: RESISTORS\FIXED; Project: AM4515_EVM_LCD; RoHS: RoHS; Temperature: -55°C+155°C; Tolerance: 1%; Voltage: NA; Wattage: 1/10W; Weight: 0.8mg; Datasheet: Y:\MIS_DATABASE\DATASHEETS\RESISTORS\PAN-ERJSER_NOV17.PDF
R646 = RESISTOR: RES 680K 1/10W 1% 0402; Chkd/date: SUHAS/200411; Crtd /date: MAZHAR/180411; Custom_Duty: 15%; Customs_HS_Code: 85332119; Distributor_name: DIGIKEY; Distributor_part_number: P680KLCT-ND; Footprint Path: Y:\MIS_DATABASE\Library\ALTIUM_TOOL\PCB_FOOTPRINTS\Altium_Footprint_Lib.PcbLib; Height: 0.40MM; Library Path: Y:\MIS_DATABASE\Library\ALTIUM_TOOL\SCHEMATICS_PARTS\MS_DISCRETE_Library.schlib; Mfr_name: PANASONIC-ECG; Mfr_part_number: ERJ-2RKF6803X; Mistral Part No: 110011040004-R; Package: 0402; Part_type: RESISTORS\FIXED; Project: AM4515_EVM_LCD; RoHS: RoHS; Temperature: -55°C+155°C; Tolerance: 1%; Voltage: NA; Wattage: 1/10W; Weight: 0.8mg; Datasheet: Y:\MIS_DATABASE\DATASHEETS\RESISTORS\PAN-ERJSER_NOV17.PDF
TP96 TP97 = TESTPOINT: TESTPOINT 0.56MM DRILL PTH; Chkd/date: BAVISH/040311; Crtd /date: MAZHAR/110405; Distributor_name: NA; Distributor_part_number: NA; Height: NA; Mfr_name: LOCAL; Mistral Part No: 130010010008; Package: THRU-HOLE; Project: KOPIN_MODULS; Temperature: NA; Tolerance: NA; Voltage: NA; Wattage: NA; Weight: NA; Datasheet: NA
U76 = TPS630701_VQFN-HR15: IC ADJ BUCK-BOOST CONVERTER WITH 3.6A SWITCH CURRENT VQFN-HR15; Chkd/date: ALVY/250122; Crtd /date: MANIRAJA/250122; Custom_Duty: 15%; Customs_HS_Code: 85423100; Distributor_name: DIGIKEY; Distributor_part_number: 296-TPS630702RNMRCT-ND; Footprint Path: Y:\MIS_DATABASE\Library\ALTIUM_TOOL\PCB_FOOTPRINTS\Altium_Footprint_Lib.PcbLib; Height: 1.00MM; Library Path: Y:\MIS_DATABASE\Library\ALTIUM_TOOL\SCHEMATICS_PARTS\MS_MISCPOWER_Library.schlib; Mfr_name: TEXAS INSTRUMENTS; Mistral Part No: 142022010015-R; Package: VQFN-HR15; Part_type: ICS\POWER\DC-DC CONVERTER; Project: AM62X_SKEVM; RoHS: RoHS; Temperature: -40°C+125°C; Tolerance: NA; Voltage: NA; Wattage: NA; Weight: 17.7mg; Datasheet: Y:\MIS_DATABASE\DATASHEETS\ICS\POWER\TPS630701X.PDF

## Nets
DGND: C134.2 C135.2 C136.2 C138.2 C139.2 C141.2 C142.1 C143.2 C144.1 C147.2 C149.2 C150.2 C151.2 C152.2 C153.2 C155.2 C158.2 C160.2 C164.2 C392.2 C398.2 C401.2 C409.2 C415.2 C420.2 C423.2 C424.2 C425.2 C432.2 C433.2 C517.2 C518.2 D2.2(ANODE) D9.2(ANODE) J11.A1(GND) J11.A12(GND) J11.B1(GND) J11.B12(GND) J22.2 J22.10 LD10.1(CATHODE) Q13.4(S1) Q13.7(S2) R178.2 R449.1 R465.2 R471.2 R484.2 R497.2 R643.2 R645.2 TP96.1(TP) TP97.1(TP) TP98.1(TP) TP99.1(TP) U39.4(GND) U68.20(GND) U68.51(GND) U68.59(GND) U69.1(GND) U69.2(GND) U69.3(GND) U69.7(GND) U76.4(GND) U76.10(PGND) U76.15(VSEL) ; also on sheet 1 3 14 15 16 17 18 19 20 21 22 23 24 25 26 27 28 29 30 31 32 33 34 35 36 37 38 39 40 41 42 43 44 45
VBUS_TYPEC1: C139.1 C398.1 C401.1 J11.A4(VBUS1) J11.A9(VBUS2) J11.B4(VBUS3) J11.B9(VBUS4) R182.2 U68.13(VBUS1) U69.4(IN1) U69.5(IN2) U69.6(IN3)
VBUS_TYPEC2: C147.1 C409.1 C415.1 C432.1 C433.1 C435.1 Q16.4(D1) Q16.7(D2) R515.1 U68.3(VBUS2) ; also on sheet 37 38
VCC_3V3_SYS: R696.1 ; also on sheet 3 14 15 16 20 21 22 24 25 26 27 28 29 31 32 33 34 35 36 37 38 39 40 41 42 43 44 45
VCC_5V0: C155.1 C158.1 C160.1 C161.1 C420.1 C423.1 C517.1 C518.1 Q14.4(D1) Q14.7(D2) R223.1 R483.1 R509.1 R646.1 TP70.1(TP) U76.7(VOUT) ; also on sheet 17 35 38 43
VCC_5V0_EN: U76.14(EN) ; also on sheet 15
VCC_5V0_FB: R645.1 R646.2 U76.5(FB)
VCC_5V0_PG: R509.2 U76.2(PG)
ADCIN1: R470.1 R471.1 U68.6(ADCIN1)
ADCIN2: R465.1 R466.2 U68.10(ADCIN2)
DRAIN1: U68.8(DRAIN1_1) U68.15(DRAIN1_2) U68.19(DRAIN1_3) U68.58(DRAIN1_4)
DRAIN2: U68.7(DRAIN2_1) U68.52(DRAIN2_2) U68.56(DRAIN2_3) U68.57(DRAIN2_4)
LDO_1V8: C143.1 U68.35(LDO_1V8)
LDO_3V3: C134.1 C142.2 R177.1 R179.1 R180.1 R181.1 R184.1 R185.1 R450.1 R451.1 R452.1 R457.1 R466.1 R470.2 U39.8(VCC) U68.9(LDO_3V3)
P2_PP_EXT_ENABLE: R494.2 U68.49(GPIO17/PP_EXT2)
PD_GPIO0: R625.2 U68.16(GPIO0)
PD_GPIO2: TP92.1(TP) U68.18(GPIO2)
PD_HRESET: R484.1 U68.44(HRESET)
PD_I2C_IRQ: R695.1 R696.2 ; also on sheet 41
PD_M_I2C3_IRQ: R450.2 U68.23(~{I2C3_IRQ}/GPIO7)
PD_M_I2C3_SCL: R158.1 R184.2 U68.21(I2C3_SCL/GPIO5)
PD_M_I2C3_SDA: R164.1 R181.2 U68.22(I2C3_SDA/GPIO6)
PD_MS_I2C1_IRQ: R457.2 U68.29(~{I2C1_IRQ})
PD_MS_I2C1_SCL: R157.1 R452.2 U68.27(I2C1_SCL)
PD_MS_I2C1_SDA: R163.1 R451.2 U68.28(I2C1_SDA)
PD_S_I2C2_IRQ: R695.2 U68.34(~{I2C2_IRQ})
PD_S_I2C2_SCL: R460.2 U68.32(I2C2_SCL)
PD_S_I2C2_SDA: R464.2 U68.33(I2C2_SDA)
PD_SPI_CLK: J22.7 R478.2 U39.6(CLK)
PD_SPI_MISO: J22.5 R179.2 R468.2 U39.2(DO(IO1))
PD_SPI_MOSI: J22.8 R473.2 U39.5(DI(IO0))
PD_SPI_SS: J22.9 R177.2 R480.2 U39.1(~{CS})
PD_VIN_3V3: C144.2 U68.5(VIN_3V3)
PP1_CABLE: C138.1 U68.25(PP1_CABLE)
PP2_CABLE: R483.2 U68.46(PP2_CABLE)
SoC_I2C0_SCL: R460.1 ; also on sheet 15 24 34 35 39 44
SoC_I2C0_SDA: R464.1 ; also on sheet 15 24 34 35 39 44
SoC_USB0_DRVVBUS: R492.1 R625.1 ; also on sheet 38
SPI_HOLDn: R180.2 U39.7(~{HOLD}(IO3))
SPI_WPn: R185.2 U39.3(~{WP}(IO2))
USB_TYPEC1_EARTH: C392.1 J11.SH1 J11.SH2 J11.SH3 J11.SH4 R178.1
USBC_CONN1_CC1: C136.1 D2.1(CATHODE) J11.A5(CC1) U68.24(C1_CC1)
USBC_CONN1_CC2: C135.1 D9.1(CATHODE) J11.B5(CC2) U68.26(C1_CC2)
USBC_CONN2_CC1: C152.1 U68.45(C2_CC1) ; also on sheet 37
USBC_CONN2_CC2: C151.1 U68.47(C2_CC2) ; also on sheet 37
VMAIN: C141.1 C149.1 C150.1 C153.1 C424.1 C425.1 R533.1 TP95.1(TP) U68.1(PP_HV2) U68.11(PP_HV1) U76.12(VIN) ; also on sheet 14
N17029933: LD10.2(ANODE) R182.1
N17370891: R449.2 U68.17(GPIO1)
N17824845: R468.1 U68.36(SPI_MISO/GPIO8)
N17824852: R473.1 U68.37(SPI_MOSI/GPIO9)
N17824859: R478.1 U68.38(SPI_CLK/GPIO10)
N17824866: R480.1 U68.39(~{SPI_SS}/GPIO11)
N17827086: J22.1 R157.2 R158.2
N17827089: J22.3 R163.2 R164.2
N17849698: C162.1 Q14.1(S1) Q14.2(S2) Q14.5(S3) Q14.6(S4) Q14.8(S5) Q16.1(S1) Q16.2(S2) Q16.5(S3) Q16.6(S4) Q16.8(S5) R495.1
N17850096: C161.2 C162.2 C435.2 Q14.3(G) Q16.3(G) R223.2 R495.2 R502.1 R515.2
N17935978: Q13.3(G) R492.2 R494.1 R497.1
N17936309: Q13.1(D1) Q13.2(D2) Q13.5(D3) Q13.6(D4) Q13.8(D5) R502.2
N19859568: L13.1 U76.11(L1)
N19859570: L13.2 U76.9(L2)
N19859674: R643.1 U76.6(FB2)
N19859678: R533.2 U76.1(PS/SYNC)
N19859810: C164.1 U76.3(VAUX)

Not connected (* = marked no-connect by the designer): J11 A2(TX1+)* A3(TX1-)* A6(D+_1)* A7(D-_1)* A8(SBU1)* A10(RX2-)* A11(RX2+)* B2(TX2+)* B3(TX2-)* B6(D+_2)* B7(D-_2)* B8(SBU2)* B10(RX1-)* B11(RX1+)*; J22 4* 6*; U68 30(HPD1/GPIO3)* 31(HPD2/GPIO4)* 40(GPIO12)* 41(GPIO13)* 42(GPIO14/PWM)* 43(GPIO15/PWM)* 48(GPIO16/PP_EXT1)* 50(C1_USB_P/GPIO18)* 53(C1_USB_N/GPIO19)* 54(C2_USB_P/GPIO20)* 55(C2_USB_N/GPIO21)*

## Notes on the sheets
sheet 12
- D-Note:
  Refer to the SK/EVM user's guide for the recommended power adapters.
  Using the recommended adapter is recommended for proper functioning of SK/EVM
  Reference Document:
  EVM User's Guide : https://www.ti.com/lit/pdf/SPRUJ40
  Reference section : Power Requirement
- USB TYPE-C PD CONTROLLER AND POWER SUPPLY
- D-Note:
  Add additional caps to VBUS_TYPEC1
- TYPE-C DUAL PD CONTROLLER
- Silk: TYPE-C PWR
- POWER INDICATION LED: VBUS_TYPEC1
- BP_NoWait
  Safe Configuration
- EXTERNAL POWER PATH FOR SOURCING, 5V/0.5A
- I2C Slave
   Address
- Port1
- Port2
- I2C2(Default)
- 0x38
- 0x3F
- I2C1
- 0x20
- 0x24
- V
- SPI EEPROM & PROGRAMMING HEADER
- V
sheet 13
- PERIPHERAL POWER SUPPLIES - 1
- D-Note:
  Add a jumper or 0R for isolation or
  current measurement
  Provision can be provided for
  pre-production board and can
  be deleted for production boards
  as required
- GROUND TEST POINTS
